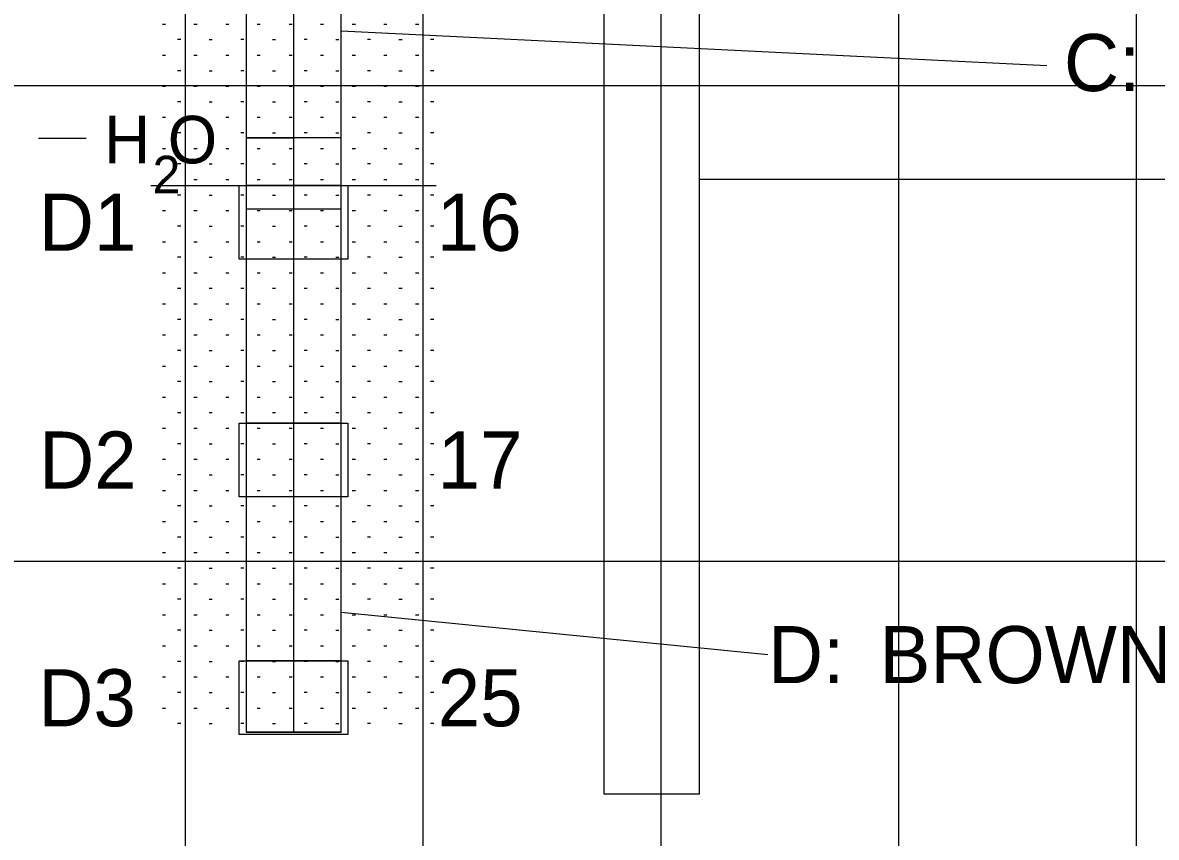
# Model space of a CAD drawing. Extents: x -290 to 297, y 616 to 861.
# Drawn here: x 3.15 to 50.83, y 678.38 to 712.65 of the extents above; entities that cross this region are included whole.
import ezdxf

# ---------------------------------------------------------------- set-up
doc = ezdxf.new("R2010")
doc.units = 0
for name, color, linetype in [('Boundary', 7, 'Continuous'), ('Cell', 7, 'Continuous'), ('Default', 7, 'Continuous'), ('DisROW Proposed Temp Easements', 7, 'Continuous'), ('Draft_4', 7, 'Continuous'), ('SewerStormPipe', 7, 'Continuous'), ('TextAlignment', 7, 'Continuous'), ('TextAlignmentSml', 7, 'Continuous'), ('V-SWLK-CONC', 7, 'Continuous')]:
    doc.layers.add(name, color=color, linetype=linetype)

msp = doc.modelspace()

# ---------------------------------------------------------------- linework, layer by layer
at = {"layer": 'Boundary'}
msp.add_line((16.546, 707.8), (12.546, 707.8), dxfattribs=at)
at = {"layer": 'Cell'}
msp.add_line((16.546, 704.8), (12.546, 704.8), dxfattribs=at)
at = {"layer": 'Default'}
for p, q in [((14.546, 743.8), (14.546, 682.8)), ((16.546, 705.8), (12.546, 705.8)), ((16.546, 682.8), (12.546, 682.8))]:
    msp.add_line(p, q, dxfattribs=at)
at = {"layer": 'DisROW Proposed Temp Easements'}
for p, q in [((5.815, 707.78), (3.815, 707.78)), ((12.546, 707.8), (14.546, 707.8))]:
    msp.add_line(p, q, dxfattribs=at)
for points in [[(12.258, 705.8), (16.834, 705.8), (16.834, 702.704), (12.258, 702.704)], [(12.258, 695.8), (16.834, 695.8), (16.834, 692.704), (12.258, 692.704)], [(12.258, 685.8), (16.834, 685.8), (16.834, 682.704), (12.258, 682.704)]]:
    msp.add_lwpolyline(points, close=True, dxfattribs=at)
at = {"layer": 'Draft_4'}
for points in [[(16.546, 726.8), (12.546, 726.8), (12.546, 705.8), (16.546, 705.8)], [(16.546, 705.8), (12.546, 705.8), (12.546, 682.8), (16.546, 682.8)]]:
    msp.add_lwpolyline(points, close=True, dxfattribs=at)
at = {"layer": 'SewerStormPipe'}
for p, q in [((16.546, 705.8), (12.546, 705.8)), ((16.546, 695.8), (12.546, 695.8)), ((16.546, 685.8), (12.546, 685.8))]:
    msp.add_line(p, q, dxfattribs=at)
at = {"layer": 'TextAlignment'}
for p, q in [((20, 630), (20, 787.989)), ((40, 630), (40, 787.989)), ((-275.612, 690), (284.208, 690))]:
    msp.add_line(p, q, dxfattribs=at)
at = {"layer": 'TextAlignmentSml'}
for p, q in [((10, 630), (10, 787.989)), ((30, 630), (30, 787.989)), ((50, 630), (50, 787.989)), ((-275.612, 710), (284.208, 710))]:
    msp.add_line(p, q, dxfattribs=at)
at = {"layer": 'V-SWLK-CONC'}
for p, q in [((9.032, 712.588), (9.164, 712.588)), ((10.352, 712.588), (10.484, 712.588)), ((11.693, 712.588), (11.825, 712.588)), ((13.013, 712.588), (13.145, 712.588)), ((14.354, 712.588), (14.486, 712.588)), ((15.674, 712.588), (15.806, 712.588)), ((17.015, 712.588), (17.147, 712.588)), ((18.335, 712.588), (18.467, 712.588)), ((19.675, 712.588), (19.807, 712.588)), ((9.667, 711.947), (9.799, 711.947)), ((10.996, 711.934), (11.128, 711.934)), ((12.327, 711.947), (12.459, 711.947)), ((13.657, 711.934), (13.789, 711.934)), ((14.988, 711.947), (15.12, 711.947)), ((16.317, 711.934), (16.449, 711.934)), ((46.23, 710.832), (16.546, 712.285)), ((17.649, 711.947), (17.781, 711.947)), ((18.978, 711.934), (19.11, 711.934)), ((20.31, 711.947), (20.442, 711.947)), ((9.032, 711.281), (9.164, 711.281)), ((10.352, 711.281), (10.484, 711.281)), ((11.693, 711.281), (11.825, 711.281)), ((13.013, 711.281), (13.145, 711.281)), ((14.354, 711.281), (14.486, 711.281)), ((15.674, 711.281), (15.806, 711.281)), ((17.015, 711.281), (17.147, 711.281)), ((18.335, 711.281), (18.467, 711.281)), ((19.675, 711.281), (19.807, 711.281)), ((9.667, 710.64), (9.799, 710.64)), ((10.996, 710.627), (11.128, 710.627)), ((12.327, 710.64), (12.459, 710.64)), ((13.657, 710.627), (13.789, 710.627)), ((14.988, 710.64), (15.12, 710.64)), ((16.317, 710.627), (16.449, 710.627)), ((17.649, 710.64), (17.781, 710.64)), ((18.978, 710.627), (19.11, 710.627)), ((20.31, 710.64), (20.442, 710.64)), ((9.032, 709.973), (9.164, 709.973)), ((10.352, 709.973), (10.484, 709.973)), ((11.693, 709.973), (11.825, 709.973)), ((13.013, 709.973), (13.145, 709.973)), ((14.354, 709.973), (14.486, 709.973)), ((15.674, 709.973), (15.806, 709.973)), ((17.015, 709.973), (17.147, 709.973)), ((18.335, 709.973), (18.467, 709.973)), ((19.675, 709.973), (19.807, 709.973)), ((9.667, 709.332), (9.799, 709.332)), ((10.996, 709.319), (11.128, 709.319)), ((12.327, 709.332), (12.459, 709.332)), ((13.657, 709.319), (13.789, 709.319)), ((14.988, 709.332), (15.12, 709.332)), ((16.317, 709.319), (16.449, 709.319)), ((17.649, 709.332), (17.781, 709.332)), ((18.978, 709.319), (19.11, 709.319)), ((20.31, 709.332), (20.442, 709.332)), ((9.032, 708.665), (9.164, 708.665)), ((10.352, 708.665), (10.484, 708.665)), ((11.693, 708.665), (11.825, 708.665)), ((13.013, 708.665), (13.145, 708.665)), ((14.354, 708.665), (14.486, 708.665)), ((15.674, 708.665), (15.806, 708.665)), ((17.015, 708.665), (17.147, 708.665)), ((18.335, 708.665), (18.467, 708.665)), ((19.675, 708.665), (19.807, 708.665)), ((9.667, 708.025), (9.799, 708.025)), ((10.996, 708.012), (11.128, 708.012)), ((12.327, 708.025), (12.459, 708.025)), ((13.657, 708.012), (13.789, 708.012)), ((14.988, 708.025), (15.12, 708.025)), ((16.317, 708.012), (16.449, 708.012)), ((17.649, 708.025), (17.781, 708.025)), ((18.978, 708.012), (19.11, 708.012)), ((20.31, 708.025), (20.442, 708.025)), ((9.032, 707.358), (9.164, 707.358)), ((10.352, 707.358), (10.484, 707.358)), ((11.693, 707.358), (11.825, 707.358)), ((13.013, 707.358), (13.145, 707.358)), ((14.354, 707.358), (14.486, 707.358)), ((15.674, 707.358), (15.806, 707.358)), ((17.015, 707.358), (17.147, 707.358)), ((18.335, 707.358), (18.467, 707.358)), ((19.675, 707.358), (19.807, 707.358)), ((9.667, 706.717), (9.799, 706.717)), ((10.996, 706.704), (11.128, 706.704)), ((12.327, 706.717), (12.459, 706.717)), ((13.657, 706.704), (13.789, 706.704)), ((14.988, 706.717), (15.12, 706.717)), ((16.317, 706.704), (16.449, 706.704)), ((17.649, 706.717), (17.781, 706.717)), ((18.978, 706.704), (19.11, 706.704)), ((20.31, 706.717), (20.442, 706.717)), ((8.546, 705.8), (20.546, 705.8)), ((9.032, 706.05), (9.164, 706.05)), ((10.352, 706.05), (10.484, 706.05)), ((11.693, 706.05), (11.825, 706.05)), ((13.013, 706.05), (13.145, 706.05)), ((14.354, 706.05), (14.486, 706.05)), ((15.674, 706.05), (15.806, 706.05)), ((17.015, 706.05), (17.147, 706.05)), ((18.335, 706.05), (18.467, 706.05)), ((19.675, 706.05), (19.807, 706.05)), ((149.968, 706.044), (31.606, 706.044)), ((9.667, 705.41), (9.799, 705.41)), ((10.996, 705.397), (11.128, 705.397)), ((12.327, 705.41), (12.459, 705.41)), ((13.657, 705.397), (13.789, 705.397)), ((14.988, 705.41), (15.12, 705.41)), ((16.317, 705.397), (16.449, 705.397)), ((17.649, 705.41), (17.781, 705.41)), ((18.978, 705.397), (19.11, 705.397)), ((20.31, 705.41), (20.442, 705.41)), ((9.032, 704.743), (9.164, 704.743)), ((10.352, 704.743), (10.484, 704.743)), ((11.693, 704.743), (11.825, 704.743)), ((13.013, 704.743), (13.145, 704.743)), ((14.354, 704.743), (14.486, 704.743)), ((15.674, 704.743), (15.806, 704.743)), ((17.015, 704.743), (17.147, 704.743)), ((18.335, 704.743), (18.467, 704.743)), ((19.675, 704.743), (19.807, 704.743)), ((9.667, 704.102), (9.799, 704.102)), ((10.996, 704.089), (11.128, 704.089)), ((12.327, 704.102), (12.459, 704.102)), ((13.657, 704.089), (13.789, 704.089)), ((14.988, 704.102), (15.12, 704.102)), ((16.317, 704.089), (16.449, 704.089)), ((17.649, 704.102), (17.781, 704.102)), ((18.978, 704.089), (19.11, 704.089)), ((20.31, 704.102), (20.442, 704.102)), ((9.032, 703.435), (9.164, 703.435)), ((10.352, 703.435), (10.484, 703.435)), ((11.693, 703.435), (11.825, 703.435)), ((13.013, 703.435), (13.145, 703.435)), ((14.354, 703.435), (14.486, 703.435)), ((15.674, 703.435), (15.806, 703.435)), ((17.015, 703.435), (17.147, 703.435)), ((18.335, 703.435), (18.467, 703.435)), ((19.675, 703.435), (19.807, 703.435)), ((9.667, 702.795), (9.799, 702.795)), ((10.996, 702.782), (11.128, 702.782)), ((12.327, 702.795), (12.459, 702.795)), ((13.657, 702.782), (13.789, 702.782)), ((14.988, 702.795), (15.12, 702.795)), ((16.317, 702.782), (16.449, 702.782)), ((17.649, 702.795), (17.781, 702.795)), ((18.978, 702.782), (19.11, 702.782)), ((20.31, 702.795), (20.442, 702.795)), ((9.032, 702.128), (9.164, 702.128)), ((10.352, 702.128), (10.484, 702.128)), ((11.693, 702.128), (11.825, 702.128)), ((13.013, 702.128), (13.145, 702.128)), ((14.354, 702.128), (14.486, 702.128)), ((15.674, 702.128), (15.806, 702.128)), ((17.015, 702.128), (17.147, 702.128)), ((18.335, 702.128), (18.467, 702.128)), ((19.675, 702.128), (19.807, 702.128)), ((9.667, 701.487), (9.799, 701.487)), ((10.996, 701.474), (11.128, 701.474)), ((12.327, 701.487), (12.459, 701.487)), ((13.657, 701.474), (13.789, 701.474)), ((14.988, 701.487), (15.12, 701.487)), ((16.317, 701.474), (16.449, 701.474)), ((17.649, 701.487), (17.781, 701.487)), ((18.978, 701.474), (19.11, 701.474)), ((20.31, 701.487), (20.442, 701.487)), ((9.032, 700.82), (9.164, 700.82)), ((10.352, 700.82), (10.484, 700.82)), ((11.693, 700.82), (11.825, 700.82)), ((13.013, 700.82), (13.145, 700.82)), ((14.354, 700.82), (14.486, 700.82)), ((15.674, 700.82), (15.806, 700.82)), ((17.015, 700.82), (17.147, 700.82)), ((18.335, 700.82), (18.467, 700.82)), ((19.675, 700.82), (19.807, 700.82)), ((9.667, 700.18), (9.799, 700.18)), ((10.996, 700.167), (11.128, 700.167)), ((12.327, 700.18), (12.459, 700.18)), ((13.657, 700.167), (13.789, 700.167)), ((14.988, 700.18), (15.12, 700.18)), ((16.317, 700.167), (16.449, 700.167)), ((17.649, 700.18), (17.781, 700.18)), ((18.978, 700.167), (19.11, 700.167)), ((20.31, 700.18), (20.442, 700.18)), ((9.032, 699.513), (9.164, 699.513)), ((10.352, 699.513), (10.484, 699.513)), ((11.693, 699.513), (11.825, 699.513)), ((13.013, 699.513), (13.145, 699.513)), ((14.354, 699.513), (14.486, 699.513)), ((15.674, 699.513), (15.806, 699.513)), ((17.015, 699.513), (17.147, 699.513)), ((18.335, 699.513), (18.467, 699.513)), ((19.675, 699.513), (19.807, 699.513)), ((9.667, 698.872), (9.799, 698.872)), ((10.996, 698.859), (11.128, 698.859)), ((12.327, 698.872), (12.459, 698.872)), ((13.657, 698.859), (13.789, 698.859)), ((14.988, 698.872), (15.12, 698.872)), ((16.317, 698.859), (16.449, 698.859)), ((17.649, 698.872), (17.781, 698.872)), ((18.978, 698.859), (19.11, 698.859)), ((20.31, 698.872), (20.442, 698.872)), ((9.032, 698.205), (9.164, 698.205)), ((10.352, 698.205), (10.484, 698.205)), ((11.693, 698.205), (11.825, 698.205)), ((13.013, 698.205), (13.145, 698.205)), ((14.354, 698.205), (14.486, 698.205)), ((15.674, 698.205), (15.806, 698.205)), ((17.015, 698.205), (17.147, 698.205)), ((18.335, 698.205), (18.467, 698.205)), ((19.675, 698.205), (19.807, 698.205)), ((9.667, 697.565), (9.799, 697.565)), ((10.996, 697.551), (11.128, 697.551)), ((12.327, 697.565), (12.459, 697.565)), ((13.657, 697.551), (13.789, 697.551)), ((14.988, 697.565), (15.12, 697.565)), ((16.317, 697.551), (16.449, 697.551)), ((17.649, 697.565), (17.781, 697.565)), ((18.978, 697.551), (19.11, 697.551)), ((20.31, 697.565), (20.442, 697.565)), ((9.032, 696.898), (9.164, 696.898)), ((10.352, 696.898), (10.484, 696.898)), ((11.693, 696.898), (11.825, 696.898)), ((13.013, 696.898), (13.145, 696.898)), ((14.354, 696.898), (14.486, 696.898)), ((15.674, 696.898), (15.806, 696.898)), ((17.015, 696.898), (17.147, 696.898)), ((18.335, 696.898), (18.467, 696.898)), ((19.675, 696.898), (19.807, 696.898)), ((9.667, 696.257), (9.799, 696.257)), ((10.996, 696.244), (11.128, 696.244)), ((12.327, 696.257), (12.459, 696.257)), ((13.657, 696.244), (13.789, 696.244)), ((14.988, 696.257), (15.12, 696.257)), ((16.317, 696.244), (16.449, 696.244)), ((17.649, 696.257), (17.781, 696.257)), ((18.978, 696.244), (19.11, 696.244)), ((20.31, 696.257), (20.442, 696.257)), ((9.032, 695.59), (9.164, 695.59)), ((10.352, 695.59), (10.484, 695.59)), ((11.693, 695.59), (11.825, 695.59)), ((13.013, 695.59), (13.145, 695.59)), ((14.354, 695.59), (14.486, 695.59)), ((15.674, 695.59), (15.806, 695.59)), ((17.015, 695.59), (17.147, 695.59)), ((18.335, 695.59), (18.467, 695.59)), ((19.675, 695.59), (19.807, 695.59)), ((9.667, 694.95), (9.799, 694.95)), ((10.996, 694.936), (11.128, 694.936)), ((12.327, 694.95), (12.459, 694.95)), ((13.657, 694.936), (13.789, 694.936)), ((14.988, 694.95), (15.12, 694.95)), ((16.317, 694.936), (16.449, 694.936)), ((17.649, 694.95), (17.781, 694.95)), ((18.978, 694.936), (19.11, 694.936)), ((20.31, 694.95), (20.442, 694.95)), ((9.032, 694.283), (9.164, 694.283)), ((10.352, 694.283), (10.484, 694.283)), ((11.693, 694.283), (11.825, 694.283)), ((13.013, 694.283), (13.145, 694.283)), ((14.354, 694.283), (14.486, 694.283)), ((15.674, 694.283), (15.806, 694.283)), ((17.015, 694.283), (17.147, 694.283)), ((18.335, 694.283), (18.467, 694.283)), ((19.675, 694.283), (19.807, 694.283)), ((9.667, 693.642), (9.799, 693.642)), ((10.996, 693.629), (11.128, 693.629)), ((12.327, 693.642), (12.459, 693.642)), ((13.657, 693.629), (13.789, 693.629)), ((14.988, 693.642), (15.12, 693.642)), ((16.317, 693.629), (16.449, 693.629)), ((17.649, 693.642), (17.781, 693.642)), ((18.978, 693.629), (19.11, 693.629)), ((20.31, 693.642), (20.442, 693.642)), ((9.032, 692.975), (9.164, 692.975)), ((10.352, 692.975), (10.484, 692.975)), ((11.693, 692.975), (11.825, 692.975)), ((13.013, 692.975), (13.145, 692.975)), ((14.354, 692.975), (14.486, 692.975)), ((15.674, 692.975), (15.806, 692.975)), ((17.015, 692.975), (17.147, 692.975)), ((18.335, 692.975), (18.467, 692.975)), ((19.675, 692.975), (19.807, 692.975)), ((9.667, 692.335), (9.799, 692.335)), ((12.327, 692.335), (12.459, 692.335)), ((14.988, 692.335), (15.12, 692.335)), ((17.649, 692.335), (17.781, 692.335)), ((20.31, 692.335), (20.442, 692.335)), ((10.996, 692.321), (11.128, 692.321)), ((13.657, 692.321), (13.789, 692.321)), ((16.317, 692.321), (16.449, 692.321)), ((18.978, 692.321), (19.11, 692.321)), ((9.032, 691.668), (9.164, 691.668)), ((10.352, 691.668), (10.484, 691.668)), ((11.693, 691.668), (11.825, 691.668)), ((13.013, 691.668), (13.145, 691.668)), ((14.354, 691.668), (14.486, 691.668)), ((15.674, 691.668), (15.806, 691.668)), ((17.015, 691.668), (17.147, 691.668)), ((18.335, 691.668), (18.467, 691.668)), ((19.675, 691.668), (19.807, 691.668)), ((9.667, 691.027), (9.799, 691.027)), ((10.996, 691.014), (11.128, 691.014)), ((12.327, 691.027), (12.459, 691.027)), ((13.657, 691.014), (13.789, 691.014)), ((14.988, 691.027), (15.12, 691.027)), ((16.317, 691.014), (16.449, 691.014)), ((17.649, 691.027), (17.781, 691.027)), ((18.978, 691.014), (19.11, 691.014)), ((20.31, 691.027), (20.442, 691.027)), ((9.032, 690.36), (9.164, 690.36)), ((10.352, 690.36), (10.484, 690.36)), ((11.693, 690.36), (11.825, 690.36)), ((13.013, 690.36), (13.145, 690.36)), ((14.354, 690.36), (14.486, 690.36)), ((15.674, 690.36), (15.806, 690.36)), ((17.015, 690.36), (17.147, 690.36)), ((18.335, 690.36), (18.467, 690.36)), ((19.675, 690.36), (19.807, 690.36)), ((9.667, 689.719), (9.799, 689.719)), ((10.996, 689.706), (11.128, 689.706)), ((12.327, 689.719), (12.459, 689.719)), ((13.657, 689.706), (13.789, 689.706)), ((14.988, 689.719), (15.12, 689.719)), ((16.317, 689.706), (16.449, 689.706)), ((17.649, 689.719), (17.781, 689.719)), ((18.978, 689.706), (19.11, 689.706)), ((20.31, 689.719), (20.442, 689.719)), ((9.032, 689.052), (9.164, 689.052)), ((10.352, 689.052), (10.484, 689.052)), ((11.693, 689.052), (11.825, 689.052)), ((13.013, 689.052), (13.145, 689.052)), ((14.354, 689.052), (14.486, 689.052)), ((15.674, 689.052), (15.806, 689.052)), ((17.015, 689.052), (17.147, 689.052)), ((18.335, 689.052), (18.467, 689.052)), ((19.675, 689.052), (19.807, 689.052)), ((9.667, 688.412), (9.799, 688.412)), ((10.996, 688.399), (11.128, 688.399)), ((12.327, 688.412), (12.459, 688.412)), ((13.657, 688.399), (13.789, 688.399)), ((14.988, 688.412), (15.12, 688.412)), ((16.317, 688.399), (16.449, 688.399)), ((17.649, 688.412), (17.781, 688.412)), ((18.978, 688.399), (19.11, 688.399)), ((20.31, 688.412), (20.442, 688.412)), ((9.032, 687.745), (9.164, 687.745)), ((10.352, 687.745), (10.484, 687.745)), ((11.693, 687.745), (11.825, 687.745)), ((13.013, 687.745), (13.145, 687.745)), ((14.354, 687.745), (14.486, 687.745)), ((15.674, 687.745), (15.806, 687.745)), ((16.546, 687.849), (34.496, 686.068)), ((17.015, 687.745), (17.147, 687.745)), ((18.335, 687.745), (18.467, 687.745)), ((19.675, 687.745), (19.807, 687.745)), ((9.667, 687.104), (9.799, 687.104)), ((10.996, 687.091), (11.128, 687.091)), ((12.327, 687.104), (12.459, 687.104)), ((13.657, 687.091), (13.789, 687.091)), ((14.988, 687.104), (15.12, 687.104)), ((16.317, 687.091), (16.449, 687.091)), ((17.649, 687.104), (17.781, 687.104)), ((18.978, 687.091), (19.11, 687.091)), ((20.31, 687.104), (20.442, 687.104)), ((9.032, 686.437), (9.164, 686.437)), ((10.352, 686.437), (10.484, 686.437)), ((11.693, 686.437), (11.825, 686.437)), ((13.013, 686.437), (13.145, 686.437)), ((14.354, 686.437), (14.486, 686.437)), ((15.674, 686.437), (15.806, 686.437)), ((17.015, 686.437), (17.147, 686.437)), ((18.335, 686.437), (18.467, 686.437)), ((19.675, 686.437), (19.807, 686.437)), ((9.667, 685.797), (9.799, 685.797)), ((10.996, 685.784), (11.128, 685.784)), ((12.327, 685.797), (12.459, 685.797)), ((13.657, 685.784), (13.789, 685.784)), ((14.988, 685.797), (15.12, 685.797)), ((16.317, 685.784), (16.449, 685.784)), ((17.649, 685.797), (17.781, 685.797)), ((18.978, 685.784), (19.11, 685.784)), ((20.31, 685.797), (20.442, 685.797)), ((9.032, 685.13), (9.164, 685.13)), ((10.352, 685.13), (10.484, 685.13)), ((11.693, 685.13), (11.825, 685.13)), ((13.013, 685.13), (13.145, 685.13)), ((14.354, 685.13), (14.486, 685.13)), ((15.674, 685.13), (15.806, 685.13)), ((17.015, 685.13), (17.147, 685.13)), ((18.335, 685.13), (18.467, 685.13)), ((19.675, 685.13), (19.807, 685.13)), ((9.667, 684.489), (9.799, 684.489)), ((10.996, 684.476), (11.128, 684.476)), ((12.327, 684.489), (12.459, 684.489)), ((13.657, 684.476), (13.789, 684.476)), ((14.988, 684.489), (15.12, 684.489)), ((16.317, 684.476), (16.449, 684.476)), ((17.649, 684.489), (17.781, 684.489)), ((18.978, 684.476), (19.11, 684.476)), ((20.31, 684.489), (20.442, 684.489)), ((9.032, 683.822), (9.164, 683.822)), ((10.352, 683.822), (10.484, 683.822)), ((11.693, 683.822), (11.825, 683.822)), ((13.013, 683.822), (13.145, 683.822)), ((14.354, 683.822), (14.486, 683.822)), ((15.674, 683.822), (15.806, 683.822)), ((17.015, 683.822), (17.147, 683.822)), ((18.335, 683.822), (18.467, 683.822)), ((19.675, 683.822), (19.807, 683.822)), ((9.667, 683.182), (9.799, 683.182)), ((10.996, 683.169), (11.128, 683.169)), ((12.327, 683.182), (12.459, 683.182)), ((13.657, 683.169), (13.789, 683.169)), ((14.988, 683.182), (15.12, 683.182)), ((16.317, 683.169), (16.449, 683.169)), ((17.649, 683.182), (17.781, 683.182)), ((18.978, 683.169), (19.11, 683.169)), ((20.31, 683.182), (20.442, 683.182))]:
    msp.add_line(p, q, dxfattribs=at)
msp.add_lwpolyline([(27.606, 741.2), (31.606, 741.2), (31.606, 680.2), (27.606, 680.2)], close=True, dxfattribs=at)

# ---------------------------------------------------------------- texts
at = {"layer": 'DisROW Proposed Temp Easements'}
for s, height, p in [('H O', 2.0001, (6.578, 706.728)), ('2', 1.575, (8.612, 705.472))]:
    msp.add_text(s, height=height, dxfattribs=at).set_placement(p)
at = {"layer": 'V-SWLK-CONC'}
for s, p in [('C: ', (46.946, 709.769)), ('D1', (3.83, 703.052)), ('16', (20.566, 703.052)), ('D2', (3.843, 693.052)), ('17', (20.603, 693.052)), ('D: ', (34.496, 684.868)), ('BROWN FINE TO MEDIUM SAND (Alluvium)', (39.188, 684.868)), ('D3', (3.81, 683.052)), ('25', (20.606, 683.052))]:
    msp.add_text(s, height=2.4, dxfattribs=at).set_placement(p)

doc.saveas('drawing.dxf')
